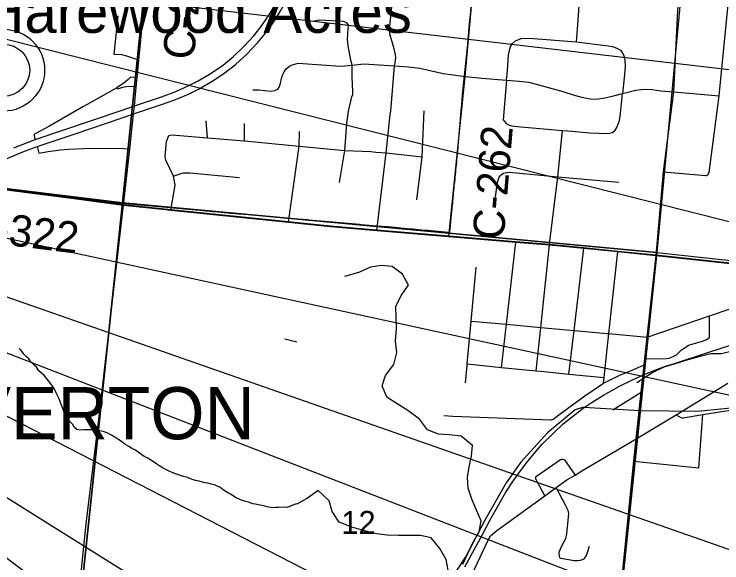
# Model space of a CAD drawing. Extents: x 0 to 34, y -3.9 to 26.2.
# Drawn here: x 6.718 to 8.005, y 16.268 to 17.265 of the extents above; entities that cross this region are included whole.
import ezdxf

# ---------------------------------------------------------------- set-up
doc = ezdxf.new("R2010")
doc.units = 0
for name, color, linetype in [('GM_X_City_Street', 7, 'Continuous'), ('GM_X_Corporation', 7, 'Continuous'), ('GM_X_Corporation_Text', 7, 'Continuous'), ('GM_X_County_Road', 7, 'Continuous'), ('GM_X_County_Road_Text', 7, 'Continuous'), ('GM_X_Interchange_Ramps', 7, 'Continuous'), ('GM_X_Interstate_Route', 7, 'Continuous'), ('GM_X_Minor_River', 7, 'Continuous'), ('GM_X_Rail_Line', 7, 'Continuous'), ('GM_X_Section', 7, 'Continuous'), ('GM_X_Section_Text', 7, 'Continuous'), ('GM_X_State_Shield', 7, 'Continuous'), ('GM_X_Township_Road', 7, 'Continuous'), ('GM_X_Unincorporated', 7, 'Continuous'), ('GM_X_Unincorporated_Text', 7, 'Continuous'), ('SH_Text', 7, 'Continuous')]:
    doc.layers.add(name, color=color, linetype=linetype)

msp = doc.modelspace()

# ---------------------------------------------------------------- linework, layer by layer
at = {"layer": 'GM_X_City_Street'}
for p, q in [((7.9171, 17.1239), (7.9995, 17.1166)), ((7.2099, 16.6753), (7.2315, 16.6696)), ((7.8065, 16.5466), (7.8581, 16.5783)), ((7.963, 16.4411), (7.9697, 16.5376)), ((7.8447, 16.4528), (7.963, 16.4411))]:
    msp.add_line(p, q, dxfattribs=at)
for points in [[(7.8986, 16.9786), (7.9751, 16.9718), (7.9766, 16.9721), (7.9781, 16.9726), (7.9789, 16.9733), (7.9798, 16.9739), (7.9805, 16.9755), (7.9812, 16.9775), (7.9995, 17.1166), (8.0236, 17.3573), (8.0237, 17.4142), (8.0271, 17.4483), (8.032, 17.4682), (8.0328, 17.4712), (8.0337, 17.473)], [(7.7402, 17.2146), (7.7434, 17.2541), (7.7466, 17.2988)], [(7.6128, 17.1451), (7.6145, 17.162), (7.6153, 17.1715), (7.6168, 17.1914), (7.62, 17.2064), (7.6237, 17.2116), (7.6294, 17.2166), (7.6396, 17.2207), (7.6544, 17.2214), (7.7402, 17.2146), (7.7979, 17.2079), (7.806, 17.2062), (7.8134, 17.2034), (7.8201, 17.1995), (7.8246, 17.1939), (7.8272, 17.188), (7.8283, 17.1821), (7.8287, 17.1694), (7.8269, 17.1495), (7.8242, 17.1212)], [(7.5378, 17.1518), (7.5572, 17.1502), (7.5679, 17.149), (7.6128, 17.1451), (7.636, 17.1433), (7.6529, 17.1413), (7.6692, 17.1374), (7.7154, 17.1247), (7.7361, 17.1181), (7.7476, 17.1147), (7.7651, 17.1114), (7.7767, 17.111), (7.7917, 17.1129), (7.8078, 17.117), (7.8242, 17.1212), (7.8481, 17.127), (7.8571, 17.1283), (7.8647, 17.1288), (7.878, 17.128), (7.8935, 17.126), (7.9171, 17.1239)], [(7.6128, 17.1451), (7.6069, 17.0732), (7.61, 17.0696), (7.6126, 17.0667), (7.6167, 17.0638), (7.6228, 17.0624), (7.6325, 17.0612), (7.7147, 17.0538), (7.7248, 17.053), (7.7646, 17.0494), (7.7974, 17.0484), (7.8055, 17.0504), (7.8103, 17.0543), (7.8139, 17.0592), (7.8186, 17.0718), (7.82, 17.0844), (7.8242, 17.1212)], [(7.6667, 16.6173), (7.6752, 16.6961), (7.6913, 16.846), (7.692, 16.8519), (7.7061, 16.9699), (7.7147, 17.0538)], [(7.5932, 16.9334), (7.5967, 16.9592), (7.5999, 16.9691), (7.6027, 16.9727), (7.6034, 16.9734), (7.6049, 16.9747), (7.6077, 16.976), (7.6103, 16.9769), (7.6145, 16.9776), (7.6183, 16.9779), (7.7061, 16.9699), (7.8171, 16.9599)], [(7.6037, 16.6235), (7.6127, 16.7017), (7.6298, 16.8512)], [(7.7265, 16.6114), (7.7358, 16.6906), (7.7533, 16.8399)], [(7.7893, 16.5946), (7.7904, 16.6051), (7.7992, 16.6849), (7.7998, 16.6902), (7.8156, 16.8337)], [(7.8851, 16.8268), (8.1771, 16.7951), (8.1938, 16.7936), (8.2544, 16.7882), (8.322, 16.7821)], [(7.5383, 16.5952), (7.5413, 16.6267), (7.5416, 16.6297), (7.5489, 16.7075), (7.5581, 16.8055)], [(7.5489, 16.7075), (7.6127, 16.7017), (7.6752, 16.6961), (7.7358, 16.6906), (7.7959, 16.6852), (7.7992, 16.6849), (7.869, 16.6786), (7.9822, 16.717), (7.984, 16.7177), (7.9878, 16.7189), (8.1703, 16.7813), (8.1711, 16.7819), (8.1716, 16.7825), (8.1726, 16.7844), (8.1771, 16.7951)], [(7.9814, 16.677), (7.9818, 16.6786), (7.9819, 16.6801), (7.9822, 16.717)], [(7.8646, 16.6389), (7.904, 16.6396), (7.9086, 16.6401), (7.912, 16.6414), (7.9175, 16.6437), (7.9219, 16.6465), (7.9304, 16.6547), (7.9413, 16.6622), (7.9439, 16.6636), (7.9565, 16.6676), (7.9695, 16.6708), (7.9753, 16.6733), (7.9814, 16.677)], [(7.4992, 16.5358), (7.5152, 16.5351), (7.6937, 16.5281), (7.695, 16.5283), (7.6965, 16.5288), (7.6983, 16.5296), (7.7003, 16.5311), (7.7107, 16.5393), (7.7556, 16.5715), (7.7876, 16.5938), (7.7893, 16.5946), (7.7993, 16.5995), (7.819, 16.6092), (7.8412, 16.6182), (7.8635, 16.628)], [(7.5416, 16.6297), (7.6037, 16.6235), (7.6667, 16.6173), (7.6756, 16.6164), (7.7265, 16.6114), (7.7904, 16.6051)], [(7.9213, 16.5375), (7.9297, 16.5326), (7.9323, 16.5319), (7.9343, 16.5318), (7.9697, 16.5376), (8.0197, 16.5459)], [(7.6825, 16.39), (7.6666, 16.4202), (7.6663, 16.4221), (7.6663, 16.4234), (7.6666, 16.4247), (7.6675, 16.4259), (7.7113, 16.4559), (7.7132, 16.4565), (7.7151, 16.4567), (7.7173, 16.4564), (7.7183, 16.4557), (7.7379, 16.4279)], [(7.7632, 16.2983), (7.7583, 16.2828), (7.7558, 16.2785), (7.7529, 16.2753), (7.7503, 16.2738), (7.7471, 16.2727), (7.7422, 16.2722), (7.7361, 16.2721), (7.7118, 16.2761), (7.7106, 16.277), (7.7099, 16.2782), (7.7093, 16.2806), (7.7087, 16.2847), (7.709, 16.2875), (7.7134, 16.2992), (7.7205, 16.3116), (7.7207, 16.3125), (7.7229, 16.3211), (7.7263, 16.3583), (7.7249, 16.3632), (7.7201, 16.3732), (7.7034, 16.405)]]:
    msp.add_lwpolyline(points, dxfattribs=at)
at = {"layer": 'GM_X_Corporation'}
msp.add_lwpolyline([(6.7163, 16.9464), (6.7265, 16.9451), (6.7291, 16.9448), (6.7453, 16.9427), (6.7463, 16.9426), (6.7583, 16.9411), (6.7609, 16.9408), (6.7715, 16.9394), (6.7741, 16.9391), (6.7865, 16.9375), (6.7872, 16.9374), (6.7881, 16.9373), (6.8002, 16.9358), (6.8013, 16.9356), (6.8023, 16.9355), (6.8117, 16.9343), (6.8135, 16.9341), (6.83, 16.932), (6.8426, 16.9304), (6.855, 16.9288), (6.8683, 16.9271), (6.881, 16.9255), (6.8933, 16.9239), (6.8941, 16.9238), (6.9135, 16.9216), (7.0008, 16.9139), (7.041, 16.9102), (7.0551, 16.909), (7.0787, 16.9068), (7.0882, 16.9059), (7.0995, 16.9049), (7.1014, 16.9047), (7.1108, 16.9039), (7.1136, 16.9037), (7.1256, 16.9027), (7.135, 16.902), (7.1449, 16.9012), (7.154, 16.9004), (7.1567, 16.9002), (7.1663, 16.8993), (7.1682, 16.8992), (7.1818, 16.8979), (7.2, 16.8963), (7.217, 16.8948), (7.2342, 16.8933), (7.251, 16.8919), (7.2527, 16.8917), (7.2901, 16.8884), (7.3461, 16.8836), (7.3493, 16.8833), (7.377, 16.8809), (7.3863, 16.8801), (7.3977, 16.8791), (7.4091, 16.878), (7.4202, 16.8771), (7.4266, 16.8765), (7.4319, 16.876), (7.4393, 16.8753), (7.4431, 16.875), (7.4526, 16.8742), (7.466, 16.873), (7.4697, 16.8726), (7.4698, 16.8726), (7.4887, 16.871), (7.5075, 16.8693), (7.5099, 16.8691), (7.5131, 16.9014), (7.5132, 16.9027), (7.5141, 16.9108), (7.5142, 16.912), (7.5144, 16.9138), (7.5151, 16.9215), (7.5154, 16.925), (7.516, 16.931), (7.5168, 16.939), (7.5169, 16.9405), (7.5178, 16.9498), (7.5181, 16.9529), (7.5187, 16.9584), (7.5188, 16.9594), (7.5194, 16.966), (7.5196, 16.9675), (7.5197, 16.9688), (7.5206, 16.9782), (7.521, 16.9815), (7.5216, 16.9874), (7.5224, 16.9956), (7.5225, 16.997), (7.5228, 17.0002), (7.5235, 17.0067), (7.5239, 17.0109), (7.5239, 17.0119), (7.5242, 17.0142), (7.5251, 17.0252), (7.5258, 17.0335), (7.526, 17.0348), (7.5268, 17.0445), (7.5271, 17.0475), (7.5276, 17.0535), (7.5283, 17.0612), (7.5283, 17.0618), (7.5285, 17.063), (7.5288, 17.0675), (7.5292, 17.0723), (7.5295, 17.076), (7.53, 17.0817), (7.5307, 17.0899), (7.5315, 17.1002), (7.533, 17.1186), (7.533, 17.1188), (7.5403, 17.1877), (7.5424, 17.2099), (7.5433, 17.2192), (7.5445, 17.2322), (7.5447, 17.2342), (7.546, 17.2482), (7.5466, 17.2544), (7.5475, 17.2635), (7.5488, 17.2774)], dxfattribs=at)
at = {"layer": 'GM_X_County_Road'}
for p, q in [((6.858, 16.9259), (6.9167, 16.9179)), ((6.9167, 16.9179), (6.9931, 16.9101))]:
    msp.add_line(p, q, dxfattribs=at)
for points in [[(7.8851, 16.8268), (7.8986, 16.9786), (7.9171, 17.1239), (7.9246, 17.2715), (7.9336, 17.3721), (7.9381, 17.4226), (7.9427, 17.4741), (7.946, 17.5071), (7.9602, 17.6472), (7.975, 17.7675)], [(7.5082, 16.8614), (7.5378, 17.1518), (7.5548, 17.3404), (7.5589, 17.3845), (7.5629, 17.4748), (7.529, 17.6609), (7.5278, 17.6669), (7.5253, 17.6705), (7.5208, 17.6763)], [(6.9167, 16.9179), (6.9279, 17.0199), (6.935, 17.0842), (6.9364, 17.0986), (6.9397, 17.1325), (6.9414, 17.1497), (6.9445, 17.1818), (6.9643, 17.3874)], [(6.4167, 16.9806), (6.6117, 16.959), (6.6303, 16.957), (6.858, 16.9259)], [(6.5955, 15.4411), (6.651, 15.5802), (6.723, 15.7542), (6.786, 15.8947), (6.7893, 15.9071), (6.7958, 15.9302), (6.8094, 16.0047), (6.8201, 16.0676), (6.8335, 16.192), (6.8484, 16.3393), (6.8718, 16.5287), (6.9167, 16.9179)], [(6.9931, 16.9101), (7.0026, 16.9091), (7.2163, 16.8873)], [(7.2163, 16.8873), (7.2928, 16.8794), (7.377, 16.8724), (7.5082, 16.8614)], [(7.5082, 16.8614), (7.6298, 16.8512), (7.6913, 16.846), (7.7533, 16.8399), (7.8156, 16.8337), (7.8851, 16.8268)], [(7.8488, 16.4934), (7.8581, 16.5783), (7.8635, 16.628), (7.8646, 16.6389), (7.869, 16.6786), (7.8851, 16.8268)], [(7.7463, 16.4329), (7.7471, 16.4334), (7.8488, 16.4934), (7.9213, 16.5375), (8.0077, 16.59), (8.0154, 16.5947)], [(7.8064, 16.0731), (7.8447, 16.4528), (7.8488, 16.4934)], [(7.5505, 16.2478), (7.5797, 16.3093), (7.584, 16.3172), (7.5956, 16.3272), (7.6825, 16.39), (7.7034, 16.405), (7.7226, 16.4189), (7.7379, 16.4279), (7.7463, 16.4329)]]:
    msp.add_lwpolyline(points, dxfattribs=at)
at = {"layer": 'GM_X_Interchange_Ramps'}
for points in [[(6.9414, 17.1497), (6.9295, 17.1509), (6.9251, 17.1464), (6.9174, 17.1399), (6.9108, 17.1355), (6.9045, 17.1315)], [(6.9045, 17.1315), (6.9004, 17.129), (6.8508, 17.1013), (6.8429, 17.0968)], [(6.9397, 17.1325), (6.9288, 17.1335), (6.9218, 17.1333), (6.9147, 17.1319), (6.9059, 17.1291), (6.9045, 17.1315)], [(6.8429, 17.0968), (6.7807, 17.0609), (6.7533, 17.0466), (6.7559, 17.0373)], [(6.7593, 17.0246), (6.7628, 17.0124), (6.7798, 17.0158), (6.8014, 17.0184), (6.8172, 17.0199), (6.8446, 17.021)], [(6.8446, 17.021), (6.8577, 17.0215), (6.917, 17.0212), (6.9279, 17.0199)]]:
    msp.add_lwpolyline(points, dxfattribs=at)
at = {"layer": 'GM_X_Interstate_Route'}
for points in [[(6.8266, 17.0474), (6.9159, 17.0776), (6.935, 17.0842), (6.9893, 17.1024), (7.0157, 17.112), (7.0358, 17.1206), (7.0543, 17.1296), (7.079, 17.1441), (7.1014, 17.1592), (7.1203, 17.1739), (7.1407, 17.1925), (7.1602, 17.2129), (7.1729, 17.2285), (7.1887, 17.2493), (7.2012, 17.2697), (7.2159, 17.2961), (7.231, 17.3309), (7.2571, 17.3959), (7.269, 17.427), (7.3104, 17.5296)], [(6.7559, 17.0373), (6.9124, 17.0903), (6.9364, 17.0986), (6.9859, 17.1151), (7.0119, 17.1246), (7.0341, 17.1349), (7.0525, 17.144), (7.0757, 17.158), (7.0981, 17.1731), (7.1167, 17.1881), (7.1362, 17.2068), (7.1535, 17.2255), (7.1683, 17.2446), (7.1816, 17.2639), (7.1949, 17.2865)], [(6.6208, 16.9492), (6.6278, 16.9549), (6.6303, 16.957), (6.6562, 16.9754), (6.677, 16.9879), (6.7064, 17.0033), (6.7336, 17.0149), (6.7593, 17.0246), (6.8266, 17.0474)], [(6.7174, 17.0222), (6.7559, 17.0373)], [(8.1769, 16.7957), (7.8848, 16.8273), (7.8154, 16.8342), (7.7531, 16.8404), (7.6911, 16.8465), (7.6295, 16.8517), (7.508, 16.8619), (7.3768, 16.8729), (7.2926, 16.88), (7.216, 16.8878), (7.0024, 16.9097), (6.9164, 16.9185), (6.6275, 16.9554)], [(6.6275, 16.9554), (6.9164, 16.9185), (7.0024, 16.9097), (7.216, 16.8878), (7.2926, 16.88), (7.3768, 16.8729), (7.508, 16.8619), (7.6295, 16.8517), (7.6911, 16.8465), (7.7531, 16.8404), (7.8154, 16.8342), (7.8848, 16.8273), (8.1769, 16.7957)]]:
    msp.add_lwpolyline(points, dxfattribs=at)
at = {"layer": 'GM_X_Minor_River'}
for points in [[(7.5335, 16.2661), (7.5426, 16.2851), (7.5518, 16.3045), (7.5632, 16.325), (7.567, 16.3448), (7.5582, 16.3642), (7.5498, 16.384), (7.5434, 16.4038), (7.5418, 16.4232), (7.5453, 16.443), (7.5491, 16.4623), (7.551, 16.4814), (7.5308, 16.4985), (7.5087, 16.5008), (7.4892, 16.5023), (7.4694, 16.5099), (7.4549, 16.5293), (7.4336, 16.5453), (7.4141, 16.5574), (7.3951, 16.5692), (7.3871, 16.5898), (7.3928, 16.6088), (7.408, 16.6286), (7.4137, 16.6502), (7.411, 16.6708), (7.4129, 16.694), (7.4122, 16.713), (7.4118, 16.7339), (7.4217, 16.7541), (7.435, 16.7731), (7.424, 16.7929), (7.4049, 16.8069), (7.3851, 16.8088), (7.3657, 16.8054), (7.3455, 16.7963), (7.3252, 16.7902), (7.3182, 16.7887)], [(7.2306, 16.3753), (7.2144, 16.3687), (7.2079, 16.3693), (7.1984, 16.3689), (7.1927, 16.3692), (7.1878, 16.3686), (7.1779, 16.3702), (7.1715, 16.3719), (7.1614, 16.3739), (7.1568, 16.3748), (7.1519, 16.3758), (7.1437, 16.3784), (7.1365, 16.3802), (7.1294, 16.3828), (7.1216, 16.3866), (7.1168, 16.3894), (7.1123, 16.3923), (7.106, 16.3956), (7.0975, 16.4012), (7.0915, 16.4057), (7.0867, 16.4074), (7.0822, 16.4099), (7.0762, 16.4112), (7.0698, 16.413), (7.0645, 16.414), (7.054, 16.4167), (7.0476, 16.4181), (7.0416, 16.4199), (7.0359, 16.422), (7.0311, 16.4238), (7.0254, 16.4255), (7.0202, 16.4273), (7.0127, 16.4295), (7.0048, 16.4325), (6.9996, 16.4349), (6.9936, 16.4379), (6.9888, 16.4403), (6.9825, 16.444), (6.9773, 16.4477), (6.9673, 16.4545), (6.9595, 16.4594), (6.9539, 16.4615), (6.9458, 16.4676), (6.9384, 16.4728), (6.932, 16.4758), (6.9272, 16.479), (6.9187, 16.4839), (6.9128, 16.4891), (6.9083, 16.4916), (6.9009, 16.4968), (6.8946, 16.5005), (6.8883, 16.5038), (6.8797, 16.5072), (6.8702, 16.5087), (6.8631, 16.5098), (6.8498, 16.5103), (6.8444, 16.5102), (6.8372, 16.5097), (6.8315, 16.5107), (6.8271, 16.5147), (6.8236, 16.5205), (6.8188, 16.5253), (6.8148, 16.53), (6.8105, 16.5355), (6.8088, 16.5413), (6.8064, 16.549), (6.8033, 16.5559), (6.8016, 16.5617), (6.7992, 16.5675), (6.7943, 16.5772), (6.7918, 16.5826), (6.7879, 16.5885), (6.7839, 16.594), (6.7788, 16.6007), (6.7723, 16.6085), (6.7628, 16.6173), (6.7581, 16.6236), (6.7537, 16.6283), (6.7489, 16.6331), (6.7442, 16.639), (6.7395, 16.6433), (6.7351, 16.6477), (6.7319, 16.6531), (6.7275, 16.6575)], [(8.0235, 16.6529), (8.0041, 16.6483), (7.9843, 16.6483), (7.9625, 16.6426), (7.9427, 16.6369), (7.9195, 16.6301), (7.8993, 16.6236), (7.8791, 16.6141), (7.86, 16.6019), (7.8501, 16.5951)], [(7.5084, 16.2249), (7.4878, 16.2349), (7.5072, 16.2551), (7.503, 16.2745), (7.4916, 16.2942), (7.4763, 16.3136), (7.4565, 16.3182), (7.437, 16.3178), (7.4165, 16.3178), (7.3959, 16.3186), (7.3764, 16.3212), (7.3528, 16.3273), (7.3315, 16.3334), (7.309, 16.3425), (7.2962, 16.3616), (7.2907, 16.3813), (7.2706, 16.3996), (7.2511, 16.3859), (7.2317, 16.3749), (7.2306, 16.3753)]]:
    msp.add_lwpolyline(points, dxfattribs=at)
at = {"layer": 'GM_X_Rail_Line'}
msp.add_line((7.7534, 16.5507), (7.7511, 16.5508), dxfattribs=at)
for points in [[(7.5375, 16.2611), (7.5691, 16.3196), (7.5844, 16.3488), (7.6012, 16.3786), (7.6119, 16.397), (7.6233, 16.4143), (7.6352, 16.4313), (7.6477, 16.4476), (7.6632, 16.4671), (7.6778, 16.4839), (7.6976, 16.5036), (7.7162, 16.5207), (7.7523, 16.5493), (7.767, 16.5589), (7.7892, 16.5728), (7.8183, 16.5891), (7.8407, 16.6), (7.8661, 16.6116), (7.8827, 16.6184), (7.9021, 16.6254), (7.9182, 16.6308), (7.9808, 16.651), (8.084, 16.6844)], [(7.7511, 16.5508), (7.7376, 16.5465), (7.6876, 16.5044), (7.6389, 16.4512), (7.6124, 16.4138), (7.5727, 16.3444), (7.5395, 16.2809), (7.4908, 16.2066)], [(8.9, 15.9724), (8.8703, 16.0388), (8.819, 16.1095), (8.6393, 16.2573), (8.4103, 16.3212), (8.3557, 16.3419), (8.3331, 16.3607), (8.2013, 16.5302), (8.1507, 16.5531), (8.1045, 16.5577), (7.961, 16.5433), (7.8546, 16.5443), (7.7534, 16.5507)]]:
    msp.add_lwpolyline(points, dxfattribs=at)
at = {"layer": 'GM_X_Section'}
for points in [[(5.9742, 18.0677), (7.0185, 17.9275), (6.9147, 16.9222), (5.8743, 17.0495)], [(7.0185, 17.9275), (7.9734, 17.7662), (7.8864, 16.832), (6.9147, 16.9222)], [(5.8743, 17.0495), (6.9147, 16.9222), (6.8082, 15.9151), (5.7775, 16.0372)], [(6.9147, 16.9222), (7.8864, 16.832), (7.7738, 15.7526), (6.8082, 15.9151)], [(7.8864, 16.832), (8.8743, 16.7258), (8.7783, 15.7191), (7.7738, 15.7526)]]:
    msp.add_lwpolyline(points, close=True, dxfattribs=at)
at = {"layer": 'GM_X_State_Shield'}
msp.add_lwpolyline([(8.9, 16.9823), (8.9, 17.736), (7.9734, 17.7662), (7.8864, 16.832), (8.8743, 16.7258)], close=True, dxfattribs=at)
at = {"layer": 'GM_X_Township_Road'}
for p, q in [((7.0692, 17.0406), (7.0669, 17.0716)), ((7.1368, 17.035), (7.1363, 17.0664))]:
    msp.add_line(p, q, dxfattribs=at)
for points in [[(7.4017, 17.0828), (7.4024, 17.0888), (7.4095, 17.1713), (7.4108, 17.1769), (7.4118, 17.186), (7.4114, 17.1914), (7.4089, 17.2023), (7.4066, 17.2107), (7.4012, 17.2272), (7.4009, 17.2286), (7.4008, 17.2307), (7.4008, 17.2347), (7.4011, 17.2431), (7.4127, 17.362)], [(6.9445, 17.1818), (6.9226, 17.1889), (6.9133, 17.191), (6.8998, 17.1919), (6.9069, 17.2621)], [(7.3091, 16.9593), (7.3191, 17.0173), (7.3228, 17.0668), (7.3258, 17.0888), (7.332, 17.1151), (7.3333, 17.1193), (7.3337, 17.1217), (7.3337, 17.1238), (7.3326, 17.1512), (7.3321, 17.1726), (7.3302, 17.1816), (7.325, 17.2075), (7.3236, 17.2206), (7.3244, 17.2282), (7.3253, 17.239), (7.3254, 17.2451), (7.3225, 17.2494), (7.3164, 17.2521), (7.2732, 17.254), (7.2601, 17.2519)], [(7.1519, 17.1275), (7.1632, 17.1276), (7.1838, 17.1255), (7.1918, 17.1264), (7.1971, 17.129), (7.2003, 17.1338), (7.2023, 17.1399), (7.2039, 17.1482), (7.2054, 17.1545), (7.2087, 17.1606), (7.2124, 17.1661), (7.2159, 17.1689), (7.2213, 17.1726), (7.2344, 17.1761), (7.3114, 17.1704), (7.3321, 17.1726), (7.3537, 17.1752), (7.4095, 17.1713), (7.4347, 17.1692), (7.4556, 17.1668), (7.4709, 17.1633), (7.4846, 17.1602), (7.4984, 17.1571), (7.5378, 17.1518)], [(7.4502, 16.9276), (7.4594, 17.0059), (7.4633, 17.0896)], [(7.377, 16.8724), (7.3943, 17.0133), (7.4017, 17.0828)], [(7.2163, 16.8873), (7.2357, 17.0254), (7.2364, 17.0517)], [(7.0026, 16.9091), (7.0105, 16.9546), (7.0073, 16.971), (6.9934, 16.9998), (6.9927, 17.0027), (6.9924, 17.0067), (6.9945, 17.0336), (6.9987, 17.045), (7.0042, 17.0457), (7.0692, 17.0406), (7.1368, 17.035), (7.2357, 17.0254), (7.3191, 17.0173), (7.366, 17.0155), (7.3754, 17.0147)], [(7.3754, 17.0147), (7.3943, 17.0133), (7.4594, 17.0059)], [(7.0073, 16.971), (7.0188, 16.975), (7.0257, 16.9768), (7.0299, 16.977), (7.0374, 16.9769), (7.1272, 16.9686)]]:
    msp.add_lwpolyline(points, dxfattribs=at)
at = {"layer": 'GM_X_Unincorporated'}
for radius in [0.0744, 0.0472]:
    msp.add_circle((6.6988, 17.1633), radius, dxfattribs=at)
at = {"layer": 'SH_Text'}
for points in [[(9.5912, 16.9819), (9.5912, 16.4915), (5.9803, 17.4022)], [(9.5912, 16.2318), (9.5912, 15.7425), (5.8947, 17.034)], [(9.6746, 15.4992), (9.6746, 15.0088), (5.7921, 17.0032)], [(9.6066, 14.5701), (9.6066, 14.0797), (5.8602, 16.9149)]]:
    msp.add_lwpolyline(points, close=True, dxfattribs=at)

# ---------------------------------------------------------------- texts
at = {"layer": 'GM_X_Corporation_Text'}
msp.add_text('SILVERTON', height=0.0947, rotation=0, dxfattribs=at).set_placement((6.4376, 16.4929))
at = {"layer": 'GM_X_County_Road_Text'}
for s, rotation, p in [('C-269', 84.4812, (7.0443, 17.1809)), ('C-262', 85.305, (7.6077, 16.854)), ('C-322', 352.8417, (6.6262, 16.8558))]:
    msp.add_text(s, height=0.05682, rotation=rotation, dxfattribs=at).set_placement(p)
at = {"layer": 'GM_X_Section_Text'}
msp.add_text('12', height=0.04186, rotation=0, dxfattribs=at).set_placement((7.3127, 16.3208))
at = {"layer": 'GM_X_Unincorporated_Text'}
msp.add_text('Harewood Acres', height=0.078977, rotation=0, dxfattribs=at).set_placement((6.6602, 17.2312))

doc.saveas('drawing.dxf')
